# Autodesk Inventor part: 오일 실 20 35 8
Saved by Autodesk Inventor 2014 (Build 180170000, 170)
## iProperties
Created: 2026-05
Part Number: 오일 실 20 35 8
Material: 고무
Document SubType Name: Modeling
Designer: dg
Density: 0.93 g/cm^3
Appearance: 고무 - 검은색 - 버전 1.1
Mass: 2.1154 g
Surface Area: 34.3949 cm^2
Volume: 2.27462 cm^3
Author: jhkim
Description: 오일-실
Creation Date: 2026-04-23
Sending System: Autodesk Inventor 2027
Preprocessor: ST-DEVELOPER v20.1
Author: dg
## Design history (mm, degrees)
node "오일 실 20 35 81"
body "Solid1"
node "기준1"
